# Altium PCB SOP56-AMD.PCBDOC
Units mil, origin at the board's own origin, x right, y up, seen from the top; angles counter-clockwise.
Board outline 1247.64 x 3931.89 mil, 2 copper layers (Top Layer, Bottom Layer); 12 components, 340 nets, 214 pads, 73 vias.
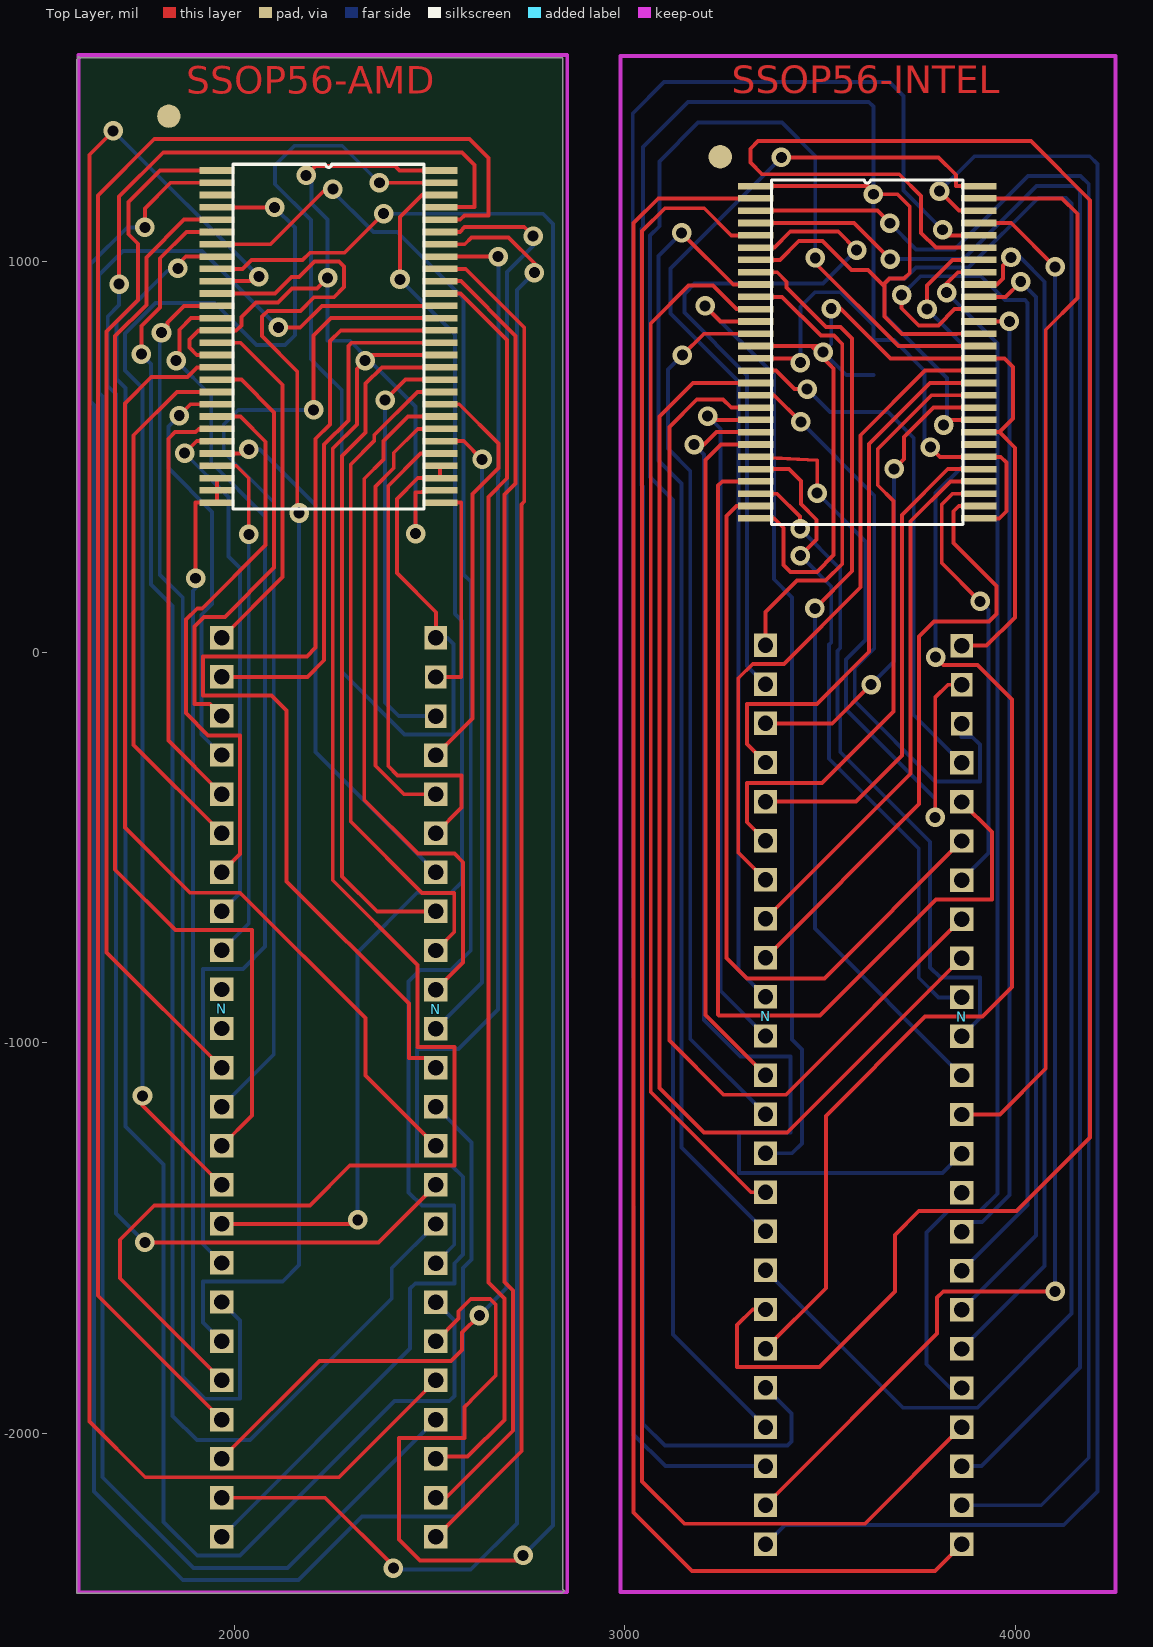
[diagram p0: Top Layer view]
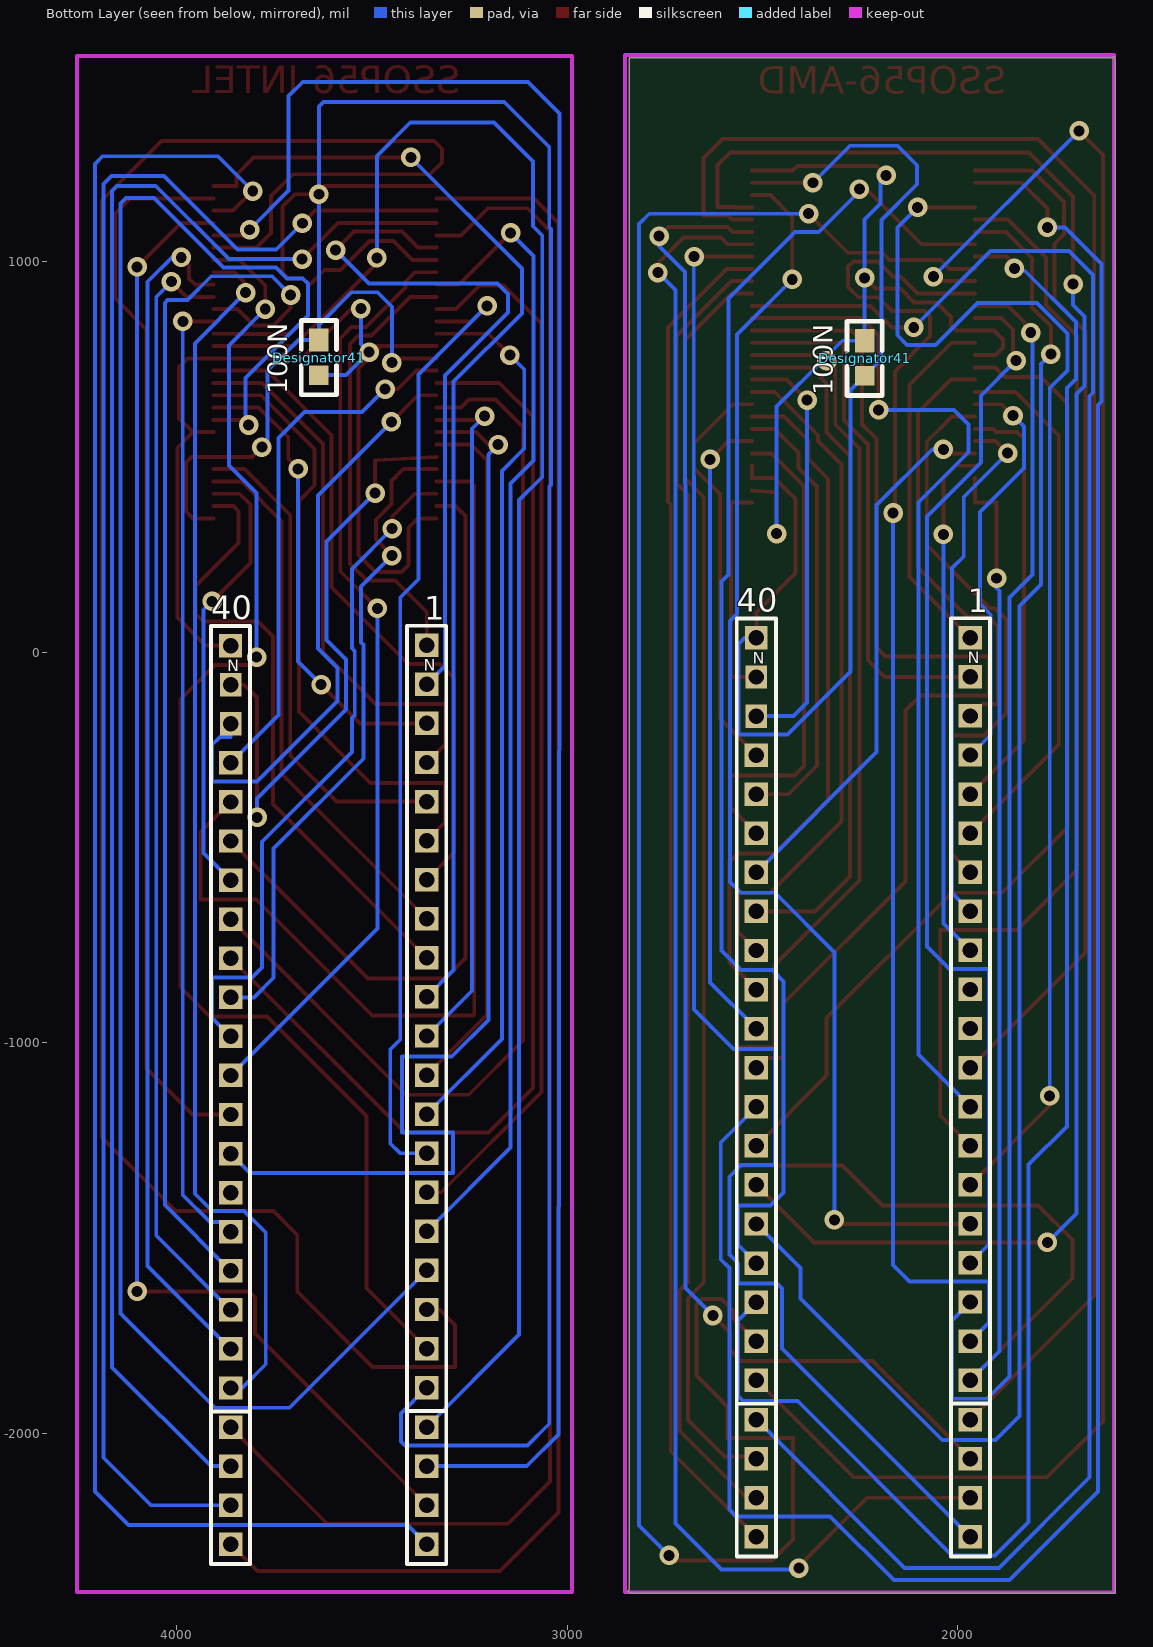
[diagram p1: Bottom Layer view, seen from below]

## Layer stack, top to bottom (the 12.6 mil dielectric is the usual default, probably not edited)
Top Layer: signal copper 1.4
Dielectric: dielectric 12.6, FR-4, Dk 4.8
Bottom Layer: signal copper 1.4

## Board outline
1599.21,1523.62 1601.18,1521.65 2840.94,1521.65 2840.94,-2398.43 2844.88,-2402.36 2838.98,-2408.27 1597.24,-2408.27 1597.24,1517.72 1603.15,1523.62

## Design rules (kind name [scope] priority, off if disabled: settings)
Clearance [All] p1: gap=12
ComponentClearance [All] p1 off: gap=10 collisioncheckmode=3 verticalgap=10 showdistances=FALSE
FabricationTestPointUsage TestPointUsage [All] p1: valid=0 allowmultiple=FALSE
FabricationTestpoint Testpoint [All] p1: side=3 testpointundercomponent=TRUE minsize=40 maxsize=100 preferedsize=60 minholesize=0 maxholesize=40 preferedholesize=32 testpointgrid=1 allowsidetop=TRUE allowsidebottom=TRUE usegrid=TRUE gridtolerance=0.01
HoleSize [All] p1: absolutevalues=TRUE maxlimit=1000 minlimit=1 maxpercent=80.000 minpercent=20.000
PolygonConnect [All] p1: connectstyle=Relief reliefconductorwidth=10 reliefentries=4 polygonreliefangle="90 Angle"
RoutingVias [All] p1: holewidth=28 width=50 viastyle="Through Hole" minholewidth=28 minwidth=50 maxholewidth=28 maxwidth=50
ShortCircuit [All] p1 off: allowed=FALSE
SilkscreenOverComponentPads [All] p1: minsilkscreentomaskgap=10
SolderMaskExpansion [All] p1: expansion=4
Width [All] p1: maxlimit=1000 minlimit=10 preferedwidth=10
22 further rules are at their usual default settings.

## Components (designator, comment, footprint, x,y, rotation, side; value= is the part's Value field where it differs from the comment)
Designator41 "100N" 0805 2239,797 r270 bottom
Designator41 "100N" 0805 3635.85,798.97 r270 bottom
N "40" SIP20A#1 2516.13,36.46 r270 top
N "1" SIP20A#2 1968.13,36.79 r270 top
N "40" SIP20A#3 3861.77,16.65 r270 top
N "1" SIP20A#2 3359.77,17.65 r270 top
? "Comment" SOP56 1956,1233 r0 top
? "Comment" sip4#1 2516.13,-1964.2 r270 bottom
? "Comment" sip4#1 1968.13,-1964.2 r270 bottom
? "Comment" sip4#1 3861.77,-1983.35 r270 bottom
? "Comment" sip4#2 3359.77,-1983.35 r270 bottom
? "Comment" SOP56 3334.85,1192.97 r0 top

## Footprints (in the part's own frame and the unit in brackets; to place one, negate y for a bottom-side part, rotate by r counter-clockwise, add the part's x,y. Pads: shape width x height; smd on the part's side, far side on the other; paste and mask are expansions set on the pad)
0805 [mil]
  rect 60x50 smd: 1(0,0)
  rect 50x50 smd: 2(90,0)
  silkscreen extent -50,-45 140,45
sip4#1 [mil]
  rect 60x60 hole 39.37 mask+4: 25(300,0) 26(200,0) 27(100,0) 28(0,0)
  silkscreen extent -50,-50 350,50
sip4#2 [mil]
  rect 60x60 hole 39.37 mask+4: 21(0,0) 22(100,0) 23(200,0) 24(300,0)
  silkscreen extent -50,-50 350,50
SIP20A#1 [mil]
  rect 60x60 hole 39.37: 21(1900,0) 22(1800,0) 23(1700,0) 24(1600,0) 25(1500,0) 26(1400,0) 27(1300,0) 28(1200,0) 29(1100,0) 30(1000,0) 31(900,0) 32(800,0) 33(700,0) 34(600,0) 35(500,0) 36(400,0) 37(300,0)
  rect 60x55 hole 39.37: 38(200,0) 39(100,0)
  rect 60x58 hole 39.37: 40(0,0)
SIP20A#2 [mil]
  rect 60x60 hole 39.37: 1(0,0) 2(100,0) 3(200,0) 4(300,0) 5(400,0) 6(500,0) 7(600,0) 8(700,0) 9(800,0) 10(900,0) 11(1000,0) 12(1100,0) 13(1200,0) 14(1300,0) 15(1400,0) 16(1500,0) 17(1600,0) 18(1700,0) 19(1800,0) 20(1900,0)
SIP20A#3 [mil]
  rect 60x60 hole 39.37: 29(1900,0) 30(1800,0) 31(1700,0) 32(1600,0) 33(1500,0) 34(1400,0) 35(1300,0) 36(1200,0) 37(1100,0) 38(1000,0) 39(900,0) 40(800,0) 41(700,0) 42(600,0) 43(500,0) 44(400,0) 45(300,0)
  rect 60x55 hole 39.37: 46(200,0) 47(100,0)
  rect 60x58 hole 39.37: 48(0,0)
SOP56 [mil]
  rect 90x17 smd: 1(0,0) 2(0,-31.5) 3(0,-62.99) 4(0,-94.49) 5(0,-125.98) 6(0,-157.48) 7(0,-188.98) 8(0,-220.47) 9(0,-251.97) 10(0,-283.46) 11(0,-314.96) 12(0,-346.46) 13(0,-377.95) 14(0,-409.45) 15(0,-440.95) 16(0,-472.44) 17(0,-503.94) 18(0,-535.43) 19(0,-566.93) 20(0,-598.43) 21(0,-629.92) 22(0,-661.42) 23(0,-692.91) 24(0,-724.41) 25(0,-755.91) 26(0,-787.4) 27(0,-818.9) 28(0,-850.39) 29(570.87,-850.39) 30(570.87,-818.9) 31(570.87,-787.4) 32(570.87,-755.91) 33(570.87,-724.41) 34(570.87,-692.91) 35(570.87,-661.42) 36(570.87,-629.92) 37(570.87,-598.43) 38(570.87,-566.93) 39(570.87,-535.43) 40(570.87,-503.94) 41(570.87,-472.44) 42(570.87,-440.95) 43(570.87,-409.45) 44(570.87,-377.95) 45(570.87,-346.46) 46(570.87,-314.96) 47(570.87,-283.46) 48(570.87,-251.97) 49(570.87,-220.47) 50(570.87,-188.98) 51(570.87,-157.48) 52(570.87,-125.98) 53(570.87,-94.49) 54(570.87,-62.99) 55(570.87,-31.5) 56(570.87,0)
  silkscreen extent 41,-866 530,16

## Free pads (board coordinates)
  round 60 smd: 0(1832.68,1372.05) 0(3243.7,1267.72)

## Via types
v1: diameter 50, hole 28, Top Layer to Bottom Layer, 73 vias

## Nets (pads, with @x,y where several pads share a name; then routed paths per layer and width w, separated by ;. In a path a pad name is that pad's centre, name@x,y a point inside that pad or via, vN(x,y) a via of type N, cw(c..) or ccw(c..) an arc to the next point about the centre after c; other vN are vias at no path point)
a0: ?.13@1956,855.05 N.17@1968.13,-1563.21 | length 2743.9
  Top Layer w10: v1(1851.21,746.24) 1863.39,758.42 1859.45,762.36 1859.45,825.2 1889.3,855.05 ?.13@1956,855.05
  Bottom Layer w10: v1(1851.21,746.24) 1941.21,656.24 1941.21,485.24 2079.21,347.24 2079.21,-753.76 2022.21,-810.76 1920.21,-810.76 1920.21,-1515.29 N.17@1968.13,-1563.21
a1: ?.12@1956,886.54 N.18@1968.13,-1663.21 | length 3312.6
  Top Layer w10: v1@1829.21,817.24 1829.21,844.17 1871.58,886.54 ?.12@1956,886.54
  Bottom Layer w10: v1@1829.21,817.24 1829.21,812.24 1809.21,792.24 1809.21,199.24 1868.21,140.24 1868.21,-1853.76 1925.21,-1910.76 2015.21,-1910.76 2015.21,-1710.29 N.18@1968.13,-1663.21
  other v1: 1813.78,817.72
a2: ?.11@1956,918.04 N.19@1968.13,-1763.21 | length 3561
  Top Layer w10: ?.11@1956,918.04 2104.01,918.04 2146.21,960.24 2165.21,960.24 2205.21,1000.24 2267.71,1000.24 2281.21,986.74 2281.21,934.54 2255.21,908.54 2204.51,908.54 2169.21,873.24 2085.71,873.24 2071.21,858.74 2071.21,808.74 2161.21,718.74 2161.21,361.24 v1(2166.21,356.24)
  Bottom Layer w10: N.19@1968.13,-1763.21 1920.21,-1715.29 1920.21,-1610.76 2124.21,-1610.76 2166.21,-1568.76 v1(2166.21,356.24)
a3: ?.10@1956,949.54 N.21 | length 5016.8
  Top Layer w10: v1(1690.21,1334.24) 1629.21,1273.24 1629.21,-1968.76 1772.21,-2111.76 2267.91,-2111.76 N.21 ; ?.10@1956,949.54 2051.5,949.54 v1(2063.21,961.24)
  Bottom Layer w10: v1(1690.21,1334.24) v1(2063.21,961.24)
a4: ?.9@1956,981.03 N.22 | length 5730.7
  Top Layer w10: ?.9@1956,981.03 2021.21,981.03 2043.68,1003.5 2175.21,1003.5 2193.95,1022.24 2282.21,1022.24 v1(2382.21,1122.24) ; N.22 2574.21,-1705.46 2574.21,-1686.76 2605.21,-1655.76 2655.21,-1655.76 2669.21,-1669.76 2669.21,-1851.66 2605.21,-1915.66 2605.21,-1916.76 2589.76,-1932.2 2589.76,-2011.2 2422.05,-2011.2 2422.05,-2271.26 2475.59,-2324.8 2726.16,-2324.8 v1(2739.21,-2311.76)
  Bottom Layer w10: v1(2382.21,1122.24) 2790.21,1122.24 2816.21,1096.24 2816.21,-2234.76 v1(2739.21,-2311.76)
a5: ?.8@1956,1012.53 N.23 | length 4688.3
  Top Layer w10: v1@1873.21,976.24 1858.66,990.79 1858.66,995.28 1875.91,1012.53 ?.8@1956,1012.53
  Bottom Layer w10: v1@1873.21,976.24 1829.21,976.24 1698.21,845.24 1698.21,699.06 1721.21,676.06 1721.21,-1213.76 1819.21,-1311.76 1819.21,-2225.76 1905.21,-2311.76 2015.21,-2311.76 2410.21,-1916.76 2550.21,-1916.76 2563.21,-1903.76 2563.21,-1710.62 N.23
  other v1: 1855.91,982.28
a6: ?.7@1956,1044.02 N.24 | length 3516.1
  Top Layer w10: ?.7@1956,1044.02 2092.99,1044.02 v1@2240.21,1191.24
  Bottom Layer w10: v1@2240.21,1191.24 2356.28,1075.17 2417.28,1075.17 2587.21,905.24 2587.21,198.74 2605.21,180.74 2605.21,-763.76 2555.21,-813.76 2475.21,-813.76 2446.21,-842.76 2446.21,-1382.54 2480.21,-1416.54 2563.13,-1416.54 2563.13,-1516.54 N.24
  other v1: 2252.36,1185.43
a7: ?.6@1956,1075.52 N.25 | length 4163.7
  Top Layer w10: v1(1762.21,763.06) 1762.21,834.34 1810.24,882.37 1810.24,1008.27 1877.49,1075.52 ?.6@1956,1075.52
  Bottom Layer w10: v1(1762.21,763.06) 1787.21,738.06 1787.21,173.24 1842.21,118.24 1842.21,-1954.76 1904.21,-2016.76 2040.21,-2016.76 2403.21,-1653.76 2403.21,-1576.46 N.25
a8: ?.28@1968.13,-1964.2 ?.52@2526.87,1107.02 | length 4620.1
  Top Layer w10: ?.28@1968.13,-1964.2 1651.21,-1647.29 1651.21,1169.24 1795.21,1313.24 2602.5,1313.24 2651.18,1264.57 2651.18,1117.76 2589.21,1117.76 2578.46,1107.02 ?.52@2526.87,1107.02
a9: ?.27@1968.13,-2064.2 ?.51@2526.87,1075.52 | length 3909.4
  Top Layer w10: ?.27@1968.13,-2064.2 2218.57,-1813.76 2555.21,-1813.76 2583.21,-1785.76 2583.21,-1741.76 v1(2627.21,-1697.76) ; ?.51@2526.87,1075.52 2577.32,1075.52 2589.7,1087.9 2742.29,1087.9 v1(2765.08,1065.11)
  Bottom Layer w10: v1(2627.21,-1697.76) 2697.21,-1627.76 2697.21,429.24 2698.21,430.24 2698.21,973.24 2765.08,1040.11 v1(2765.08,1065.11)
a10: ?.26@1968.13,-2164.2 ?.50@2526.87,1044.02 | length 4399.2
  Top Layer w10: ?.26@1968.13,-2164.2 2232.66,-2164.2 v1@2416.21,-2347.76 ; ?.50@2526.87,1044.02 2589.99,1044.02 2607,1061.03 2702.42,1061.03 2768.08,995.38 v1(2768.08,971.59)
  Bottom Layer w10: v1@2416.21,-2347.76 2605.21,-2347.76 2723.21,-2229.76 2723.21,926.72 v1(2768.08,971.59)
  other v1: 2407.09,-2344.09
a11: ?.25@1968.13,-2264.2 ?.49@2526.87,1012.53 | length 3987.3
  Top Layer w10: ?.49@2526.87,1012.53 v1(2675.21,1012.53)
  Bottom Layer w10: ?.25@1968.13,-2264.2 2450.21,-1782.12 2450.21,-1628.76 2463.21,-1615.76 2563.21,-1615.76 2563.21,-1563.93 2585.13,-1542.01 2585.13,-1342.67 2555.21,-1312.76 2468.21,-1312.76 2468.21,-1015.76 2574.21,-1015.76 2675.21,-914.76 2675.21,450.24 2676.21,451.24 2676.21,1011.53 v1(2675.21,1012.53)
a12: ?.25@2516.13,-2264.2 ?.48@2526.87,981.03 | length 3466.5
  Top Layer w10: ?.25@2516.13,-2264.2 2735.21,-2045.12 2735.21,378.24 2742.21,385.24 2742.21,831.24 2592.42,981.03 ?.48@2526.87,981.03
a13: ?.26@2516.13,-2164.2 ?.47@2526.87,949.54 | length 3342.6
  Top Layer w10: ?.26@2516.13,-2164.2 2541.7,-2164.2 2713.21,-1992.7 2713.21,-1633.76 2691.21,-1611.76 2691.21,403.24 2720.21,432.24 2720.21,809.24 2579.92,949.54 ?.47@2526.87,949.54
a14: ?.27@2516.13,-2064.2 ?.46@2526.87,918.04 | length 3273.1
  Top Layer w10: ?.27@2512.6,-2059.06 2596.85,-2059.06 2691.21,-1964.7 2691.21,-1653.76 2671.21,-1633.76 2650.79,-1613.33 2650.79,397.64 2698.21,445.07 2698.21,799.24 2579.41,918.04 ?.46@2526.87,918.04 ; ?.27@2516.13,-2064.2 ?.27@2540.53,-2039.8
a15: ?.28@2516.13,-1964.2 ?.45@2526.87,886.54 | length 5189.7
  Top Layer w10: v1(2113.21,831.24) 2168.97,831.24 2224.27,886.54 ?.45@2526.87,886.54
  Bottom Layer w10: v1(2113.21,831.24) 1917.21,1027.24 1715.64,1027.24 1654.21,965.82 1654.21,664.06 1663.21,655.06 1663.21,-2111.76 1895.21,-2343.76 2136.57,-2343.76 ?.28@2516.13,-1964.2
a16: ?.44@2526.87,855.05 N.13@1968.13,-1163.21 | length 2632.1
  Top Layer w10: v1(2203.21,620.24) 2203.21,810.24 2248.01,855.05 ?.44@2526.87,855.05
  Bottom Layer w10: N.13@1968.13,-1163.21 2101.21,-1030.13 2101.21,383.73 1973.21,511.73 1973.21,583.24 2010.21,620.24 v1(2203.21,620.24)
a17: ?.5@1956,1107.02 N.14@1968.13,-1263.21 | length 2819.5
  Top Layer w10: ?.5@1956,1107.02 1871.58,1107.02 1775.21,1010.64 1775.21,889.06 1695.21,809.06 1695.21,-556.76 1849.21,-710.76 2045.28,-710.76 2045.28,-1186.06 N.14@1968.13,-1263.21
a18: ?.4@1956,1138.51 N.15@1968.13,-1363.21 | length 3299.1
  Top Layer w10: v1(1765.21,-1135.76) 1765.21,-1160.29 N.15@1968.13,-1363.21 ; ?.4@1956,1138.51 v1(2103.21,1138.51)
  Bottom Layer w10: v1(1765.21,-1135.76) 1765.21,676.06 1720.21,721.06 1720.21,815.24 1798.21,893.24 1950.21,893.24 2057.21,786.24 2130.21,786.24 2155.21,811.24 2155.21,1086.51 v1(2103.21,1138.51)
a19: ?.53@2526.87,1138.51 N.26 | length 4701.5
  Top Layer w10: v1(1705.21,942.24) 1705.21,1166.24 1818.21,1279.24 2582.96,1279.24 2615.35,1246.85 2615.35,1139.76 2566.87,1139.76 2566.87,1138.51 ?.53@2526.87,1138.51 ; v1(1771.21,-1510.76) 2368.91,-1510.76 N.26
  Bottom Layer w10: v1(1705.21,942.24) 1705.21,888.24 1676.21,859.24 1676.21,681.06 1696.96,660.31 1696.96,-1436.51 v1(1771.21,-1510.76)
a20: ?.54@2526.87,1170.01 N.16@1968.13,-1463.21 | length 3278.3
  Top Layer w10: N.16@1968.13,-1463.21 v1@2315.75,-1463.21 ; v1(2424.21,954.24) 2424.21,1114.01 2480.21,1170.01 ?.54@2526.87,1170.01
  Bottom Layer w10: v1@2315.75,-1463.21 2315.75,-768.21 2468.21,-615.76 2555.21,-615.76 2583.21,-587.76 2583.21,80.24 2565.21,98.24 2565.21,813.24 v1(2424.21,954.24)
  other v1: 2316.14,-1452.76
a21: ?.43@2526.87,823.55 N.29@2516.13,-1063.54 | length 2818.4
  Top Layer w10: N.29@2516.13,-1063.54 2491.72,-1039.14 2447.13,-1039.14 2447.13,-899.62 2134.21,-586.7 2134.21,-149.76 2095.21,-110.76 1920.21,-110.76 1920.21,-10.76 2185.73,-10.76 2208.21,11.72 2208.21,546.24 2245.21,583.24 2245.21,796.24 2272.52,823.55 ?.43@2526.87,823.55
a22: ?.42@2526.87,792.05 N.2@1968.13,-63.21 | length 1347.9
  Top Layer w10: N.2@1968.13,-63.21 2187.72,-63.21 2230.21,-20.72 2230.21,531.24 2292.21,593.24 2292.21,783.74 2300.52,792.05 ?.42@2526.87,792.05
a23: ?.15@1956,792.05 N.1@1968.13,36.79 | length 924.8
  Top Layer w10: ?.15@1956,792.05 2016.35,792.05 2124,684.4 2124,192.66 N.1@1968.13,36.79
a24: ?.29@2526.87,382.61 N.39@2516.13,-63.54 | length 565.4
  Top Layer w10: N.39@2516.13,-63.54 2581.1,-63.54 2581.1,382.61 ?.29@2526.87,382.61
a25: N.11@1968.13,-963.21
a26: N.10@1968.13,-863.21
b1: 
b2: 
b3: 
b4: 
b5: 
b6: 
b7: 
b8: 
b9: 
b10: 
b11: 
b12: 
b13: 
b14: 
b16: 
b17: 
b18: 
b19: 
b20: 
b21: 
b22: 
byte: 
ce: 
CE1: 
CS: 
D0: ?.18@1956,697.57 N.3@1968.13,-163.21 | length 1125.7
  Top Layer w10: ?.18@1956,697.57 2018.21,697.57 2102,613.78 2102,216.27 1975.89,90.16 1922.12,90.16 1898.21,66.24 1898.21,-132.76 1937.67,-132.76 N.3@1968.13,-163.21
D1: ?.20@1956,634.57 N.4@1968.13,-263.21 | length 1068.3
  Top Layer w10: v1(1859.21,605.57) 1888.21,634.57 ?.20@1956,634.57
  Bottom Layer w10: v1(1859.21,605.57) 1831.21,577.57 1831.21,471.24 1943.23,359.23 1943.23,122.82 1916.21,95.8 1916.21,-211.29 N.4@1968.13,-263.21
D2: ?.22@1956,571.58 N.5@1968.13,-363.21 | length 1101.5
  Top Layer w10: ?.22@1956,571.58 1909.27,571.58 1901.21,563.52 1848.49,563.52 1831.21,546.24 1831.21,-226.29 N.5@1968.13,-363.21
D3: ?.24@1956,508.59 N.34@2516.13,-563.54 | length 1383.6
  Top Layer w10: ?.24@1956,508.59 2026.56,508.59 v1(2037.21,519.24)
  Bottom Layer w10: v1(2037.21,519.24) 2065.84,519.24 2208.21,376.88 2208.21,-255.62 N.34@2516.13,-563.54
D4: ?.33@2526.87,508.59 N.35@2516.13,-463.54 | length 1257
  Top Layer w10: N.35@2516.13,-463.54 2581.89,-397.78 2581.89,-315.76 2418.21,-315.76 2394.21,-291.76 2394.21,425.59 2477.21,508.59 ?.33@2526.87,508.59
D5: ?.35@2526.87,571.58 N.36@2516.13,-363.54 | length 1149.6
  Top Layer w10: N.36@2516.13,-363.54 2434,-363.54 2361.21,-290.76 2361.21,424.12 2408.34,471.24 2408.34,510.37 2469.55,571.58 ?.35@2526.87,571.58
D6: ?.37@2526.87,634.57 N.37@2516.13,-263.54 | length 1055
  Top Layer w10: N.37@2516.13,-263.54 2609.45,-170.22 2609.45,404.48 2676.21,471.24 2676.21,534.24 2575.88,634.57 ?.37@2526.87,634.57
D7: ?.39@2526.87,697.57 N.38@2516.13,-163.54 | length 1080.7
  Top Layer w10: v1(2386.21,645.24) 2438.53,697.57 ?.39@2526.87,697.57
  Bottom Layer w10: v1(2386.21,645.24) 2386.21,-128.76 2421,-163.54 N.38@2516.13,-163.54
D8: ?.19@1956,666.07 N.6@1968.13,-463.21 | length 1371.7
  Top Layer w10: ?.19@1956,666.07 1853.11,666.07 1742.21,555.17 1742.21,-237.29 N.6@1968.13,-463.21
D9: ?.21@1956,603.08 N.7@1968.13,-563.21 | length 1469.7
  Top Layer w10: ?.21@1956,603.08 2015.59,603.08 2080,538.66 2080,274.03 1918.21,112.24 1905.21,112.24 1876.21,83.24 1876.21,-155.76 1933.21,-212.76 2015.21,-212.76 2015.21,-516.13 N.7@1968.13,-563.21
D10: ?.23@1956,540.09 N.8@1968.13,-663.21 | length 1346.3
  Top Layer w10: v1(1873.21,509.24) 1904.05,540.09 ?.23@1956,540.09
  Bottom Layer w10: v1(1873.21,509.24) 1985.21,397.24 1985.21,245.24 2015.21,215.24 2015.21,-616.13 N.8@1968.13,-663.21
D11: ?.25@1956,477.09 N.9@1968.13,-763.21 | length 1331.4
  Top Layer w10: ?.25@1956,477.09 2005.21,477.09 2037.21,445.09 v1(2037.21,301.24)
  Bottom Layer w10: N.9@1968.13,-763.21 2037.21,-694.13 v1(2037.21,301.24)
D12: ?.34@2526.87,540.09 N.30@2516.13,-963.54 | length 1632.4
  Top Layer w10: ?.34@2526.87,540.09 2587.37,540.09 v1(2634.21,493.24)
  Bottom Layer w10: N.30@2516.13,-963.54 2634.21,-845.46 v1(2634.21,493.24)
D13: ?.36@2526.87,603.08 N.31@2516.13,-863.54 | length 1782.6
  Top Layer w10: N.31@2516.13,-863.54 2585.13,-794.54 2585.13,-537.67 2563.21,-515.76 2470.21,-515.76 2332.75,-378.29 2332.75,443.96 2382.03,493.24 2382.03,540.19 2444.92,603.08 ?.36@2526.87,603.08
D14: ?.38@2526.87,666.07 N.32@2516.13,-763.54 | length 1735.5
  Top Layer w10: N.32@2516.13,-763.54 2563.13,-716.54 2563.13,-616.54 2481,-616.54 2298.21,-433.76 2298.21,480 2358.21,540 2358.21,555.24 2469.04,666.07 ?.38@2526.87,666.07
D15: ?.40@2526.87,729.06 N.33@2516.13,-663.54 | length 1771
  Top Layer w10: N.33@2516.13,-663.54 2365.96,-663.54 2276.21,-573.79 2276.21,502 2336.21,562 2336.21,687.24 2378.03,729.06 ?.40@2526.87,729.06
D16: 
D17: 
D18: 
D19: 
D20: 
D21: 
D22: 
D23: 
D24: 
D25: 
D26: 
D27: 
D28: 
D29: 
D30: 
D31: 
D32: 
D33: 
D34: 
D35: 
D36: 
D37: 
D38: 
D39: 
D40: 
D41: 
D42: 
D43: 
D44: 
D45: 
D46: 
D47: 
D48: 
D49: 
D50: 
D51: 
D52: 
D53: 
D54: 
D55: 
D56: 
GND: ?.14@1956,823.55 ?.16@1956,760.56 ?.26@1956,445.6 ?.27@1956,414.1 ?.28@1956,382.61 ?.30@2526.87,414.1 ?.41@2526.87,760.56 ?.56@2526.87,1233 Designator41.1@2239,797 N.20@1968.13,-1863.21 | length 8633.4
  Top Layer w10: v1(1901.21,189.24) 1901.21,382.61 1956,382.61 1956,414.1 ?.26@1956,445.6 ; ?.16@1956,760.56 1904.01,760.56 1885.04,779.53 1885.04,800.57 1908.02,823.55 1956,823.55 2005.21,823.55 2018.21,836.55 2018.21,858.24 2055.21,895.24 2112.32,895.24 2147.62,930.54 2211.51,930.54 v1(2239.21,958.24) ; N.20@1968.13,-1863.21 1707.21,-1602.29 1707.21,-1503.76 1795.21,-1415.76 2193.69,-1415.76 2295.69,-1313.76 2563.21,-1313.76 2563.21,-1010.76 2469.13,-1010.76 2469.13,-800.67 2252.21,-583.76 2252.21,521.24 2314.21,583.24 2314.21,725.24 v1(2335.21,746.24) 2349.52,760.56 ?.41@2526.87,760.56 ; v1(2183.71,1220.5) 2208.07,1244.86 2411.44,1244.86 2423.3,1233 ?.56@2526.87,1233 ; v1(2464.21,303.24) 2464.21,408.24 ?.30@2526.87,414.1
  Bottom Layer w10: v1(1901.21,189.24) 1901.21,164.24 1894.21,157.24 1894.21,-1789.29 N.20@1968.13,-1863.21 ; v1(2183.71,1220.5) 2197.92,1206.29 2197.92,1148.29 2239,1107.21 2239,958.24 v1@2239,958.03 ; v1(2239.21,958.24) v1@2239,958.03 ; v1(2335.21,746.24) v1@2341.07,752.1 ; v1(2464.21,303.24) 2464.21,628.96 v1@2341.07,752.1 ; Designator41.1@2239,797 v1@2239,958.03 ; Designator41.1@2239,797 2296.17,797 ; Designator41.1@2239,797 v1@2239,958.03 ; 2296.17,797 v1@2341.07,752.1 ; 2296.17,797 v1@2341.07,752.1
gnd1: 
gnd2: 
gnd3: 
h0: 
h1: 
h2: 
h3: 
h4: 
h5: 
h6: 
h7: 
h8: 
h9: 
h10: 
h11: 
h12: 
h13: 
h14: 
h15: 
h16: 
h17: 
h18: 
h19: 
HV: 
i0: 
i1: 
i2: 
i3: 
i4: 
i5: 
i6: 
i7: 
LE: 
m1: 
m2: 
m3: 
m4: 
m5: 
m6: 
m7: 
m8: 
m9: 
m10: 
m11: 
m12: 
m13: 
m14: 
m15: 
m16: 
m17: 
m18: 
m19: 
m20: 
m21: 
m22: 
m23: 
m24: 
m25: 
m26: 
m27: 
m28: 
m29: 
m30: 
m31: 
m32: 
m33: 
m34: 
m35: 
m36: 
m37: 
m38: 
m39: 
m40: 
MCLR: 
o0: 
o1: 
o2: 
o3: 
o4: 
o5: 
o6: 
o7: 
o8: 
o9: 
o10: 
o11: 
o12: 
o13: 
o14: 
o15: 
o16: 
oe: ?.17@1956,729.06 N.27 | length 2579.1
  Top Layer w10: ?.17@1956,729.06 1905.03,729.06 1880.21,704.24 1787.49,704.24 1720.21,636.96 1720.21,-448.76 1887.21,-615.76 2015.21,-615.76 2336.21,-936.76 2336.21,-1083.62 N.27
P1: 
P2: 
P3: 
P4: 
P5: 
P6: 
P7: 
P8: 
P9: 
P9IN: 
P10: 
P11: 
P11IN: 
P12: 
P13: 
P13IN: 
P14: 
P15: 
P16: 
P17: 
P18: 
P19: 
P20: 
P21: 
P22: 
P23: 
P24: 
P25: 
P26: 
P27: 
P28: 
P29: 
P30: 
P31: 
P32: 
P33: 
P34: 
P35: 
P36: 
P37: 
P38: 
P39: 
P40: 
P41: 
P42: 
P43: 
P44: 
P45: 
P46: 
P47: 
P48: 
q0: 
q1: 
q2: 
q3: 
q4: 
q5: 
q6: 
q7: 
RA0: 
RA1: 
RA2: 
RDY: ?.3@1956,1170.01
RES1: 
RES2: 
RST: ?.2@1956,1201.5 N.28 | length 5773.6
  Top Layer w10: v1(1771.21,1087.24) 1771.21,1135.78 1836.94,1201.5 ?.2@1956,1201.5
  Bottom Layer w10: v1(1771.21,1087.24) 1726.03,1087.24 1632.21,993.42 1632.21,642.06 1641.21,633.06 1641.21,-2147.76 1868.21,-2374.76 2164.21,-2374.76 2327.21,-2211.76 2567.71,-2211.76 2585.21,-2194.26 2585.21,-1576.46 2607.13,-1554.54 2607.13,-1254.54 N.28
S1: 
S2: 
S3: 
S4: 
S5: 
S6: 
S7: 
S8: 
S9: 
S10: 
S11: 
S12: 
S13: 
S14: 
S15: 
S16: 
S17: 
S18: 
S19: 
S21: 
S22: 
S23: 
S24: 
S25: 
S26: 
S27: 
S28: 
S29: 
S30: 
S31: 
S32: 
S33: 
S34: 
S35: 
S36: 
S37: 
S38: 
S39: 
SCK: 
SDI: 
SDO: 
TCK: 
tdI: 
tdo: 
TMS: 
VCC: ?.31@2526.87,445.6 ?.32@2526.87,477.09 ?.55@2526.87,1201.5 Designator41.2@2239,707 N.40@2516.13,36.46 | length 3046.5
  Top Layer w10: v1(2371.21,1201.5) ?.55@2526.87,1201.5 ; N.40@2516.13,36.46 2516.13,102.24 2416.21,202.16 2416.21,392.16 2469.65,445.6 2526.87,445.6 ?.32@2526.87,477.09
  Bottom Layer w10: v1(2371.21,1201.5) 2276.47,1296.24 2154.47,1296.24 2104.47,1246.24 2104.47,1197.72 2196.21,1105.98 2196.21,749.79 2239,707 2275.21,670.79 2275.21,-49.76 2436.21,-210.76 2561.21,-210.76 2561.21,21.24 2546,36.46 N.40@2516.13,36.46
vcc1: 
vcc2: 
vcc3: 
vcc3.3: 
vcc3sel: 
vcc5sel: 
vccen: 
vccen8: 
vccen12: 
vccen37: 
vccen38: 
vccsel: 
VPEN: 
vpp: 
vpp1: 
vpp31: 
vppen9: 
vppen11: 
vppen13: 
VPPH9: 
VPPH11: 
VPPH13: 
VPPL9: 
VPPL11: 
VPPL13: 
WR: ?.1@1956,1233 N.12@1968.13,-1063.21 | length 2641.1
  Top Layer w10: ?.1@1956,1233 1810.17,1233 1728.92,1151.75 1728.92,1069.62 1753.21,1045.33 1753.21,901.06 1673.21,821.06 1673.21,-768.29 N.12@1968.13,-1063.21
pads on no net: ?.1@3334.85,1192.97 ?.2@3334.85,1161.47 ?.3@3334.85,1129.98 ?.4@3334.85,1098.48 ?.5@3334.85,1066.98 ?.6@3334.85,1035.49 ?.7@3334.85,1003.99 ?.8@3334.85,972.5 ?.9@3334.85,941 ?.10@3334.85,909.5 ?.11@3334.85,878.01 ?.12@3334.85,846.51 ?.13@3334.85,815.01 ?.14@3334.85,783.52 ?.15@3334.85,752.02 ?.16@3334.85,720.53 ?.17@3334.85,689.03 ?.18@3334.85,657.53 ?.19@3334.85,626.04 ?.20@3334.85,594.54 ?.21@3334.85,563.05 ?.21@3359.77,-1983.35 ?.22@3334.85,531.55 ?.22@3359.77,-2083.35 ?.23@3334.85,500.05 ?.23@3359.77,-2183.35 ?.24@3334.85,468.56 ?.24@3359.77,-2283.35 ?.25@3334.85,437.06 ?.25@3861.77,-2283.35 ?.26@3334.85,405.57 ?.26@3861.77,-2183.35 ?.27@3334.85,374.07 ?.27@3861.77,-2083.35 ?.28@3334.85,342.57 ?.28@3861.77,-1983.35 ?.29@3905.72,342.57 ?.30@3905.72,374.07 ?.31@3905.72,405.57 ?.32@3905.72,437.06 ?.33@3905.72,468.56 ?.34@3905.72,500.05 ?.35@3905.72,531.55 ?.36@3905.72,563.05 ?.37@3905.72,594.54 ?.38@3905.72,626.04 ?.39@3905.72,657.53 ?.40@3905.72,689.03 ?.41@3905.72,720.53 ?.42@3905.72,752.02 ?.43@3905.72,783.52 ?.44@3905.72,815.01 ?.45@3905.72,846.51 ?.46@3905.72,878.01 ?.47@3905.72,909.5 ?.48@3905.72,941 ?.49@3905.72,972.5 ?.50@3905.72,1003.99 ?.51@3905.72,1035.49 ?.52@3905.72,1066.98 ?.53@3905.72,1098.48 ?.54@3905.72,1129.98 ?.55@3905.72,1161.47 ?.56@3905.72,1192.97 Designator41.1@3635.85,798.97 Designator41.2@3635.85,708.97 N.1@3359.77,17.65 N.2@3359.77,-82.35 N.3@3359.77,-182.35 N.4@3359.77,-282.35 N.5@3359.77,-382.35 N.6@3359.77,-482.35 N.7@3359.77,-582.35 N.8@3359.77,-682.35 N.9@3359.77,-782.35 N.10@3359.77,-882.35 N.11@3359.77,-982.35 N.12@3359.77,-1082.35 N.13@3359.77,-1182.35 N.14@3359.77,-1282.35 N.15@3359.77,-1382.35 N.16@3359.77,-1482.35 N.17@3359.77,-1582.35 N.18@3359.77,-1682.35 N.19@3359.77,-1782.35 N.20@3359.77,-1882.35 N.29@3861.77,-1883.35 N.30@3861.77,-1783.35 N.31@3861.77,-1683.35 N.32@3861.77,-1583.35 N.33@3861.77,-1483.35 N.34@3861.77,-1383.35 N.35@3861.77,-1283.35 N.36@3861.77,-1183.35 N.37@3861.77,-1083.35 N.38@3861.77,-983.35 N.39@3861.77,-883.35 N.40@3861.77,-783.35 N.41 N.42 N.43 N.44 N.45 N.46 N.47 N.48
copper on no net: | length 133543.7
  Top Layer w10: v1(3144.95,1073.11) 3277.06,941 3334.85,941 ; v1(3147.06,760.21) 3201.86,815.01 3334.85,815.01 ; v1(3177.06,531.21) 3202.06,531.21 3233.89,563.05 3334.85,563.05 ; v1(3205.06,886.21) 3244.76,846.51 3334.85,846.51 ; v1(3211.73,604.21) 3221.4,594.54 3334.85,594.54 ; 3334.85,342.57 3382.06,342.57 3406.06,318.57 3406.06,223.21 3424.06,205.21 3491.06,205.21 3534.06,248.21 3534.06,726.52 3499.71,760.87 3477.06,783.52 ; 3334.85,374.07 3285.92,374.07 3260.06,348.21 3260.06,-782.79 3312.06,-834.79 3510.33,-834.79 3861.77,-483.35 ; 3334.85,405.57 3389.56,405.57 3448.06,347.07 v1(3448.06,316.21) ; 3334.85,437.06 3248.91,437.06 3238.06,426.21 3238.06,-927.79 3240.06,-929.79 3499.06,-929.79 3796.06,-632.79 3938.98,-632.79 3938.98,-460.55 3861.77,-383.35 ; 3334.85,468.56 3419.71,468.56 3450.06,438.21 3450.06,379.02 3490.06,339.02 3490.06,288.21 v1(3449.06,247.21) ; 3334.85,500.05 3492.06,491.21 v1(3492.06,407.21) ; 3334.85,531.55 3246.16,531.55 3206.06,491.45 3206.06,-928.63 3359.77,-1082.35 ; 3334.85,626.04 3272.06,626.04 3251.12,646.97 3183.82,646.97 3113.49,576.64 3113.49,-994.22 3252.06,-1132.79 3412.33,-1132.79 3861.77,-683.35 ; 3334.85,657.53 3381.74,657.53 v1(3450.06,589.21) ; 3334.85,689.03 3174.18,689.03 3088.06,602.91 3088.06,-1115.79 3202.06,-1229.79 3415.33,-1229.79 3861.77,-783.35 ; 3334.85,720.53 3386.57,720.53 3433.89,673.21 v1(3466.06,673.21) ; 3334.85,752.02 3438.25,752.02 v1(3449.06,741.21) ; 3334.85,878.01 3285.26,878.01 3225.06,938.21 3163.06,938.21 3066.06,841.21 3066.06,-1125.79 3322.62,-1382.35 3359.77,-1382.35 ; 3334.85,909.5 3402.06,909.5 3501.35,810.21 3534.82,810.21 3556.06,788.97 3556.06,226.21 3513.06,183.21 3440.27,183.21 3359.77,102.72 3359.77,17.65 ; 3334.85,972.5 3389.69,972.5 3413.97,948.21 3413.97,933.21 3514.96,832.21 3552.06,832.21 3581.06,803.21 3581.06,207.21 v1(3486.06,112.21) ; 3334.85,1003.99 3396.62,1003.99 3444.84,1052.21 3506.06,1052.21 3580.06,978.21 3622.06,978.21 3664.06,936.21 ; 3334.85,1035.49 3382.34,1035.49 3423.06,1076.21 3545.91,1076.21 v1(3593.06,1029.06) ; 3334.85,1066.98 3272.06,1066.98 3202.83,1136.21 3102.06,1136.21 3044.06,1078.21 3044.06,-2122.79 3152.06,-2230.79 3614.33,-2230.79 3861.77,-1983.35 ; 3334.85,1098.48 3586.29,1098.48 v1(3678.56,1006.21) ; 3334.85,1129.98 3645.94,1129.98 v1(3678.06,1097.86) ; 3334.85,1161.47 3085.32,1161.47 3022.06,1098.21 3022.06,-2201.79 3172.06,-2351.79 3793.33,-2351.79 3861.77,-2283.35 ; 3334.85,1192.97 3621.99,1192.97 v1@3639.37,1175.59 ; 3359.77,-2183.35 3799.06,-1744.06 3799.06,-1651.29 3814.56,-1635.79 v1(4101.06,-1635.79) ; 3359.77,-1782.35 3514.06,-1628.06 3514.06,-1186.79 3768.06,-932.79 3915.06,-932.79 3990.55,-857.3 3990.55,-121.28 3902.06,-32.79 3815.06,-32.79 v1(3795.06,-12.79) ; 3359.77,-1682.35 3327.06,-1682.35 3287.01,-1722.4 3287.01,-1829.79 3498.06,-1829.79 3691.06,-1636.79 3691.06,-1491.79 3752.06,-1430.79 4002.06,-1430.79 4190.55,-1242.3 4190.55,1156.72 4039.06,1308.21 3340.5,1308.21 3320.87,1288.58 3320.87,1253.54 3351.2,1223.21 3702.06,1223.21 3758.06,1167.21 3758.06,1073.21 3795.78,1035.49 3905.72,1035.49 ; 3359.77,-782.35 3753.06,-389.06 3753.06,40.65 3791.06,78.65 3931.5,78.65 3951.06,98.21 3951.06,169.21 3841.06,279.21 3841.06,360.71 3854.42,374.07 3905.72,374.07 ; 3359.77,-682.35 3731.06,-311.06 3731.06,335.21 3832.91,437.06 3905.72,437.06 ; 3359.77,-582.35 3290.06,-512.63 3290.06,-66.79 3327.06,-29.79 3407.06,-29.79 3603.06,166.21 3603.06,555.21 3768.37,720.53 3905.72,720.53 ; 3359.77,-482.35 3312.77,-435.35 3312.77,-334.79 3504.27,-334.79 3687.06,-151.99 3687.06,387.21 3647.06,427.21 3647.06,520.29 3784.31,657.53 3905.72,657.53 ; 3359.77,-382.35 3591.06,-382.35 3709.06,-264.35 3709.06,351.56 3826.06,468.56 3905.72,468.56 ; 3359.77,-282.35 3312.06,-234.63 3312.06,-132.79 3491.06,-132.79 3625.06,1.21 3625.06,533.21 3780.88,689.03 3905.72,689.03 ; 3359.77,-182.35 3530.5,-182.35 v1(3630.06,-82.79) ; v1(3400.52,1266.21) 3802.82,1266.21 3847.06,1221.98 3847.06,1192.97 3905.72,1192.97 ; v1(3487.06,1009.21) 3487.06,996.52 3700.06,783.52 3905.72,783.52 ; v1(3507.06,768.21) 3491.75,783.52 3477.06,783.52 ; v1(3528.06,879.21) 3552.06,879.21 3679.25,752.02 3905.72,752.02 3971.6,752.02 3993.31,730.31 3993.31,598.13 3958.23,563.05 ; v1(3635.85,1171.98) 3697.23,1171.98 3729.03,1140.18 3729.03,970.68 3714.56,956.21 3677.06,956.21 3664.06,943.21 3664.06,936.21 ; v1(3689.06,469.21) 3714.06,494.21 3714.06,550.28 3789.82,626.04 3905.72,626.04 ; v1(3708.06,914.21) 3708.06,880.21 3752.06,836.21 3802.06,836.21 3843.86,878.01 3905.72,878.01 ; v1(3773.06,878.21) 3773.06,938.21 3838.84,1003.99 3905.72,1003.99 ; v1(3781.72,525.05) 3806.72,500.05 3905.72,500.05 3961.72,500.05 3976.06,485.71 3976.06,360.71 3957.92,342.57 3905.72,342.57 ; v1(3794.06,-422.79) 3794.06,-116.35 3827.06,-83.35 3861.77,-83.35 ; v1(3805.06,1179.98) 3855.06,1129.98 3905.72,1129.98 ; v1(3813.06,1081.21) 3827.29,1066.98 3905.72,1066.98 ; v1(3823.06,920.21) 3823.06,943.5 3852.06,972.5 3905.72,972.5 ; v1@3824.06,580.21 3838.39,594.54 3905.72,594.54 ; 3861.77,-1183.35 3959.57,-1183.35 4077.06,-1065.85 4077.06,825.17 4158.06,906.17 4158.06,1122.16 4118.75,1161.47 3905.72,1161.47 ; 3861.77,16.65 3925.5,16.65 3998.06,89.21 3998.06,523.21 3958.23,563.05 ; 3905.72,405.57 3838.41,405.57 3810.76,377.91 3810.76,228.52 v1(3909.06,130.21) ; 3905.72,563.05 3958.23,563.05 ; 3905.72,815.01 3850.06,815.01 3849.26,814.21 3709.06,814.21 3664.06,859.21 ; 3905.72,846.51 v1(3984.06,846.51) ; 3905.72,909.5 3974.35,909.5 v1(4013.06,948.21) ; 3905.72,941 3952.06,941 3967.72,956.66 3967.72,989.87 v1(3988.06,1010.21) ; 3905.72,1098.48 3988.79,1098.48 v1(4101.06,986.21) ; 3477.06,783.52 3334.85,783.52 3477.06,783.52 ; 3664.06,859.21 3664.06,936.21 ; 3664.06,859.21 3664.06,936.21
  Bottom Layer w10: v1(3144.95,1073.11) 3086.03,1014.18 3086.03,490.77 3145.06,431.74 3145.06,-1267.63 3359.77,-1482.35 ; v1(3147.06,760.21) 3110.06,723.21 3110.06,520.92 3167.06,463.92 3167.06,-989.63 3359.77,-1182.35 ; v1(3177.06,531.21) 3202.06,506.21 3202.06,-941.82 3295.59,-1035.35 3423.23,-1035.35 3423.23,-1229.35 3292.13,-1229.35 3292.13,-1332.79 3812.33,-1332.79 3861.77,-1283.35 ; v1(3205.06,886.21) 3381.06,710.21 3381.06,186.66 3427.56,140.16 3427.56,-991.34 3453.15,-1016.93 3453.15,-1257.48 3428.28,-1282.35 3359.77,-1282.35 ; v1(3211.73,604.21) 3244.06,571.88 3244.06,-866.63 3359.77,-982.35 ; 3359.77,-2283.35 3409.33,-2233.79 4123.06,-2233.79 4209.06,-2147.79 4209.06,1249.71 4189.56,1269.21 3894.3,1269.21 v1(3805.06,1179.98) ; 3359.77,-2083.35 3103.62,-2083.35 3022.06,-2001.79 3020.03,331.24 3020.03,1379.18 3100.06,1459.21 3677.06,1459.21 3713.06,1423.21 3713.06,1181.21 v1(3813.06,1081.21) ; 3359.77,-1983.35 3123.06,-1746.63 3123.06,389.21 3064.03,448.24 3064.03,1066.11 3088.06,1090.13 3088.06,1256.21 3187.06,1355.21 3401.86,1355.21 3487.06,1270.01 v1(3487.06,1009.21) ; 3359.77,-1882.35 3426.06,-1948.63 3426.06,-2020.4 3415.67,-2030.79 3102.06,-2030.79 3046.06,-1974.79 3046.06,424.21 3042.03,428.24 3042.03,1083.18 3046.06,1087.21 3046.06,1292.91 3161.36,1408.21 3624.06,1408.21 3635.85,1396.42 v1(3635.85,1171.98) 3635.85,1109.42 3635.85,837.42 ; 3359.77,-1582.35 3711.22,-1933.79 3902.06,-1933.79 4143.06,-1692.79 4143.06,1148.21 4129.06,1162.21 4057.75,1162.21 3879.75,984.21 3745.06,984.21 3717.06,956.21 3677.06,956.21 3664.06,943.21 3664.06,861.4 3824.06,701.4 v1@3824.06,580.21 ; 3359.77,-882.35 3290.77,-813.35 3290.77,692.5 3116.06,867.21 3116.06,981.76 v1(3400.52,1266.21) ; 3359.77,-82.35 3312.77,-35.35 3312.77,708.5 3152.06,869.21 3152.06,917.21 3178.06,943.21 3507.21,943.21 v1(3593.06,1029.06) ; v1(3448.06,316.21) 3551.06,213.21 3551.06,10.21 3544.06,3.21 3544.06,-161.79 3551.06,-168.79 3551.06,-255.09 3781.1,-485.13 3781.1,-806.69 3807.2,-832.79 3909.06,-832.79 3909.06,-936.06 3861.77,-983.35 ; v1(3449.06,247.21) 3528.06,168.21 3528.06,25.21 3522.06,19.21 3522.06,-272.75 3752.06,-502.75 3752.06,-833.35 3802.06,-883.35 3861.77,-883.35 ; v1(3449.06,741.21) 3449.06,884.21 3486.06,921.21 3552.06,921.21 3635.85,837.42 ; v1(3450.06,589.21) 3638.06,401.21 3638.06,9.21 3588.06,-40.79 3588.06,-124.79 3794.06,-330.79 3908.77,-330.79 3908.77,-236.79 3888.77,-216.79 3861.77,-216.79 3861.77,-183.35 ; v1(3466.06,673.21) 3525.06,614.21 3673.06,614.21 3739.06,548.21 3739.06,-160.63 3861.77,-283.35 ; v1(3486.06,112.21) 3486.06,-707.63 3861.77,-1083.35 ; v1(3492.06,407.21) 3616.06,283.21 3616.06,31.21 3566.06,-18.79 3566.06,-146.79 3794.06,-374.79 v1(3794.06,-422.79) ; v1(3528.06,879.21) 3528.06,789.21 v1(3507.06,768.21) 3566.3,708.97 3635.85,708.97 ; v1(3630.06,-82.79) 3689.06,-23.79 v1(3689.06,469.21) ; v1(3678.06,1097.86) 3744.82,1031.1 3843.7,1031.1 4031.81,1219.21 4166.06,1219.21 4187.06,1198.21 4187.06,-2061.79 4065.5,-2183.35 3861.77,-2183.35 ; v1(3678.56,1006.21) 3866.29,1006.21 4053.29,1193.21 4152.06,1193.21 4165.06,1180.21 4165.06,-1830.61 3912.32,-2083.35 3861.77,-2083.35 ; v1(3708.06,914.21) 3756.06,962.21 3911.22,962.21 3972.53,900.9 4023.37,900.9 4030.06,894.21 4030.06,-1415.06 3861.77,-1583.35 ; v1(3773.06,878.21) 3866.06,785.21 3866.06,478.21 3795.06,407.21 v1(3795.06,-12.79) ; v1(3781.72,525.05) 3766.93,539.84 3766.93,720.34 3688.3,798.97 3635.85,798.97 ; v1(3823.06,920.21) 3953.06,790.21 3953.06,-1386.06 3908.77,-1430.35 3827.06,-1430.35 3771.65,-1485.75 3771.65,-1822.44 3832.56,-1883.35 3861.77,-1883.35 ; 3861.77,-1783.35 4074.06,-1571.06 4074.06,948.21 4012.06,1010.21 v1(3988.06,1010.21) ; 3861.77,-1683.35 4052.06,-1493.06 4052.06,909.21 v1(4013.06,948.21) ; 3861.77,-1483.35 3886.18,-1458.94 3914.56,-1458.94 3984.06,-1389.44 v1(3984.06,846.51) ; 3861.77,-583.35 3930.77,-514.35 3930.77,108.5 v1(3909.06,130.21) ; v1(4101.06,-1635.79) v1(4101.06,986.21) ; 3635.85,798.97 3635.85,837.42 ; 3635.85,798.97 3635.85,837.42
  other v1: 3815.75,581.5

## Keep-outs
Keep-Out Layer:
  lines w10: 1601.18,-2406.02 1601.18,1528.74 2852.36,1528.74 2852.36,-2406.02 1601.18,-2406.02 ; 2988.19,-2405.91 4255.12,-2405.9 4255.12,1525.59 2988.19,1525.59 2988.19,-2405.91

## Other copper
Top Layer:
  text "SSOP56-INTEL" at 3273.62,1431.1 h70
  text "SSOP56-AMD" at 1876.77,1429.13 h70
